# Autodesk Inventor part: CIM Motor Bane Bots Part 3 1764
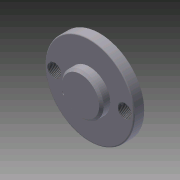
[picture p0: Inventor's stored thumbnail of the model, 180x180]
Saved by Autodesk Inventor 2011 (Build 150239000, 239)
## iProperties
Created: 2010-01
Part Number: CIM Motor Bane Bots Part 3 1764
Document SubType Name: Modeling
Designer: cmcfadden
Density: 1 g/cm^3
Author: cmcfadden
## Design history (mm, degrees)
sketch "Sketch1"
  geometry: C1 r 32.195 at (-10.853, 1.279); 1 further point
  constraints: 1 centre point
  dimensions: "d0" = 64.389 diameter of C1
extrude "Extrusion1" new body sketch "Sketch1" distance "d1" = 7.366; taper "d2" = 0 deg
fillet "Fillet1" dims "d3" = 0.79248
sketch "Sketch2"
  geometry: C1 r 31.402 at (0, 0) reference; C2 r 14.986 at (0, 0); 1 further point
  constraints: 1 centre point, 1 coincident
  dimensions: "d4" = 29.972 diameter of C2
extrude "Extrusion2" join sketch "Sketch2" distance "d5" = 6.35; taper "d6" = 0 deg
chamfer "Chamfer1" distance "d7" = 1.5875; stored, may be unused: second distance "d8" = 3.175, angle "d9" = 45 deg
sketch "Sketch3"
  geometry: C1 r 14.986 at (0, 0) reference; C2 r 4.889 at (-25.4, 0); C3 r 4.889 at (25.4, 0); C4 r 32.195 at (0, 0) reference; 1 further point
  constraints: 2 centre point
  dimensions: "d10" = 9.779 diameter of C2; "d11" = 9.779 diameter of C3; "d12" = 25.4 distance of C4.centre C2.centre; "d13" = 25.4 distance of C1.centre C3.centre
extrude "Extrusion3" cut sketch "Sketch3" stored distance "d14" = 6.35; taper "d15" = 0 deg
sketch "Sketch4"
  geometry: C1 r 1.715 at (-18.144, -10.577); C2 r 1.715 at (-12.077, -16.644); 1 further point
  constraints: 2 centre point
  dimensions: "d16" = 3.429 diameter of C1; "d17" = 3.429 diameter of C2
extrude "Extrusion4" cut sketch "Sketch4" stored distance "d18" = 6.35; taper "d19" = 0 deg
thread "Thread1" dims "d20" = 25.4, "d21" = 0
thread "Thread2" dims "d22" = 25.4, "d23" = 0
body "Solid1"
